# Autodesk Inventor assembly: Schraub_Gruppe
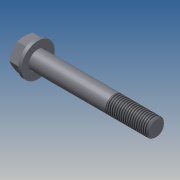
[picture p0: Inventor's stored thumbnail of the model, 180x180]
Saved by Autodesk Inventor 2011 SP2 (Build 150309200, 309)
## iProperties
Created: 2012-06
Part Number: Schraub_Gruppe
Document SubType Name: Assembly
Designer: JRE
Author: JRE
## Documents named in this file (3)
- E:\Users\jre\Documents\Inventor\Test\Schraub_Gruppe.iam
- C:\Users\JRE\Documents\Inventor\Content Center Files\R2011\de-DE\DIN 125-1  A\DIN 125 - A 17.ipt
- C:\Users\JRE\Documents\Inventor\Content Center Files\R2011\de-DE\DIN 931-1\DIN 931-1 - M16 x 110.ipt
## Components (2 placed, 2 different names)
1. DIN 125-1 A A 17:1 — Einfügen:4
2. DIN 931-1 - ersetzt durch DIN EN 24014 M16 x 110:1 — Einfügen:4
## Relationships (1: Insert 1)
- Einfügen:4 [Insert]: DIN 125-1 A A 17:1 ↔ DIN 931-1 - ersetzt durch DIN EN 24014 M16 x 110:1
